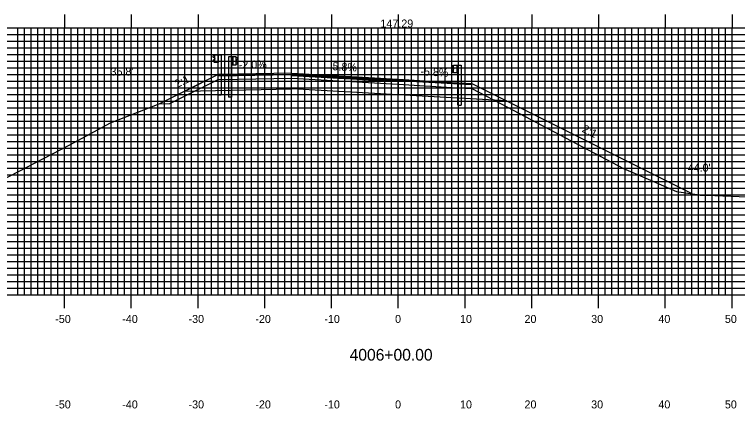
# Model space of a CAD drawing. Extents: x 851360 to 851703, y 364661 to 364881.
# Drawn here: x 851468.2 to 851576.6, y 364732.4 to 364791.4 of the extents above; entities that cross this region are included whole.
import ezdxf

# ---------------------------------------------------------------- set-up
doc = ezdxf.new("R2010")
doc.units = 0
for name, color, linetype in [('ANNOTATION', 7, 'Continuous'), ('D_Guardrail_Beam_Lt', 7, 'Continuous'), ('D_Guardrail_Beam_Rt', 7, 'Continuous'), ('D_Roadway_Centerline_Text', 7, 'Continuous'), ('D_Roadway_Edge_Shoulder', 7, 'Continuous'), ('D_Roadway_Edge_TW', 7, 'Continuous'), ('D_Roadway_Pavement', 7, 'Continuous'), ('D_Roadway_SlopeLines', 7, 'Continuous'), ('D_Roadway_SubGrade', 7, 'Continuous'), ('D_Text_Standard', 7, 'Continuous'), ('H_V ANNOTATION', 7, 'Continuous'), ('M_Guardrail', 7, 'Continuous'), ('M_Roadway_Centerline', 7, 'Continuous'), ('MAJOR', 7, 'Continuous'), ('MINOR', 7, 'Continuous'), ('S_Roadway_Centerline', 7, 'Continuous')]:
    doc.layers.add(name, color=color, linetype=linetype)

msp = doc.modelspace()

# ---------------------------------------------------------------- linework, layer by layer
at = {"layer": 'D_Guardrail_Beam_Lt'}
for p, q in [((851500.3, 364785.01), (851500.3, 364779.01)), ((851500.77, 364785.01), (851500.3, 364785.01)), ((851501.46, 364785.01), (851500.77, 364785.01)), ((851500.77, 364785.01), (851500.77, 364783.85)), ((851500.83, 364785.01), (851500.83, 364783.85)), ((851500.94, 364785.01), (851500.94, 364783.85)), ((851501.46, 364783.85), (851501.46, 364785.01)), ((851501.46, 364784.93), (851501.53, 364784.92)), ((851501.55, 364784.91), (851501.69, 364784.81)), ((851500.77, 364783.85), (851501.46, 364783.85)), ((851500.79, 364779.01), (851500.79, 364783.85)), ((851501.46, 364784.47), (851501.46, 364784.4)), ((851501.53, 364783.95), (851501.46, 364783.93)), ((851501.69, 364784.67), (851501.5, 364784.53)), ((851501.5, 364784.33), (851501.69, 364784.19)), ((851501.69, 364784.05), (851501.55, 364783.95)), ((851500.79, 364779.01), (851500.3, 364779.01))]:
    msp.add_line(p, q, dxfattribs=at)
for centre, major_axis, start_param, end_param in [((851501.52, 364784.88), (0.0417, 0), 0.959931, 1.376053), ((851501.54, 364784.47), (-0.0789, 0), 5.323254, 6.283185), ((851501.54, 364784.4), (-0.0789, 0), 6.283185, 7.243116), ((851501.52, 364783.99), (0.0417, 0), 4.907132, 5.323254), ((851501.64, 364784.74), (0.0877, 0), 5.323254, 7.243116), ((851501.64, 364784.12), (0.0877, 0), 5.323254, 7.243116)]:
    msp.add_ellipse(centre, major_axis=major_axis, ratio=0.995501, start_param=start_param, end_param=end_param, dxfattribs=at)
at = {"layer": 'D_Guardrail_Beam_Rt'}
for p, q in [((851534, 364783.78), (851534.69, 364783.78)), ((851534, 364782.62), (851534, 364783.78)), ((851534.52, 364783.78), (851534.52, 364782.62)), ((851534.62, 364783.78), (851534.62, 364782.62)), ((851534.69, 364783.78), (851535.16, 364783.78)), ((851534.69, 364783.78), (851534.69, 364782.62)), ((851535.16, 364783.78), (851535.16, 364777.78)), ((851533.91, 364783.68), (851533.77, 364783.58)), ((851533.77, 364783.43), (851533.96, 364783.3)), ((851533.96, 364783.1), (851533.77, 364782.96)), ((851533.77, 364782.82), (851533.91, 364782.72)), ((851534, 364783.7), (851533.93, 364783.68)), ((851533.93, 364782.71), (851534, 364782.7)), ((851534, 364783.23), (851534, 364783.16)), ((851534.69, 364782.62), (851534, 364782.62)), ((851534.67, 364777.78), (851534.67, 364782.62)), ((851534.67, 364777.78), (851535.16, 364777.78))]:
    msp.add_line(p, q, dxfattribs=at)
for centre, major_axis, start_param, end_param in [((851533.82, 364783.51), (-0.0877, 0), 5.323254, 7.243116), ((851533.82, 364782.89), (-0.0877, 0), 5.323254, 7.243116), ((851533.93, 364783.64), (-0.0417, 0), 4.907132, 5.323254), ((851533.93, 364782.75), (-0.0417, 0), 0.959931, 1.376053), ((851533.92, 364783.23), (0.0789, 0), 0, 0.959931), ((851533.92, 364783.16), (0.0789, 0), 5.323254, 6.283185)]:
    msp.add_ellipse(centre, major_axis=major_axis, ratio=0.995501, start_param=start_param, end_param=end_param, dxfattribs=at)
at = {"layer": 'D_Roadway_Edge_Shoulder'}
for points in [[(851509.73, 364782.59), (851501.73, 364782.43), (851501.73, 364782.43), (851498.73, 364782.37), (851498.73, 364782.2), (851509.73, 364782.39)], [(851525.73, 364781.66), (851533.73, 364781.2), (851533.73, 364781.2), (851536.73, 364781.02), (851536.73, 364780.86), (851525.73, 364781.5)]]:
    msp.add_lwpolyline(points, close=True, dxfattribs=at)
at = {"layer": 'D_Roadway_Edge_TW'}
msp.add_lwpolyline([(851509.73, 364782.59), (851525.73, 364781.66), (851525.73, 364781.5), (851509.73, 364782.39)], close=True, dxfattribs=at)
at = {"layer": 'D_Roadway_Pavement'}
msp.add_lwpolyline([(851509.73, 364782.39), (851525.73, 364781.5), (851525.73, 364781.33), (851509.73, 364782.23)], close=True, dxfattribs=at)
for points in [[(851509.73, 364782.39), (851509.73, 364782.23)], [(851525.73, 364781.5), (851525.73, 364781.33)], [(851525.73, 364781.5), (851525.73, 364781.33)], [(851525.73, 364781.5), (851525.73, 364781.33)]]:
    msp.add_lwpolyline(points, dxfattribs=at)
at = {"layer": 'D_Roadway_SlopeLines'}
for points in [[(851498.73, 364782.37), (851489.98, 364778)], [(851536.73, 364781.02), (851569.71, 364764.54)]]:
    msp.add_lwpolyline(points, dxfattribs=at)
at = {"layer": 'D_Roadway_SubGrade'}
for points in [[(851509.73, 364782.23), (851509.73, 364782.39), (851498.73, 364782.2), (851498.73, 364782.37), (851493.81, 364779.91), (851509.73, 364780.23)], [(851509.73, 364782.23), (851525.73, 364781.33), (851525.73, 364779.33), (851509.73, 364780.23)], [(851525.73, 364781.33), (851525.73, 364781.5), (851536.73, 364780.86), (851536.73, 364781.02), (851541.94, 364778.42), (851525.73, 364779.33)]]:
    msp.add_lwpolyline(points, close=True, dxfattribs=at)
at = {"layer": 'M_Guardrail'}
for p, q in [((851498.14, 364785.24), (851498, 364785.14)), ((851498, 364784.99), (851498.2, 364784.86)), ((851498.24, 364785.26), (851498.16, 364785.24)), ((851498.24, 364785.33), (851498.73, 364785.33)), ((851498.24, 364784.16), (851498.24, 364785.33)), ((851498.73, 364785.33), (851499.22, 364785.33)), ((851498.73, 364785.33), (851498.73, 364784.16)), ((851499.22, 364785.33), (851499.22, 364779.33)), ((851498.2, 364784.64), (851498, 364784.5)), ((851498, 364784.36), (851498.14, 364784.26)), ((851498.16, 364784.25), (851498.24, 364784.24)), ((851498.23, 364784.79), (851498.23, 364784.7)), ((851498.73, 364784.16), (851498.24, 364784.16)), ((851498.73, 364779.33), (851498.73, 364784.16)), ((851498.73, 364779.33), (851499.22, 364779.33))]:
    msp.add_line(p, q, dxfattribs=at)
for centre, major_axis, start_param, end_param in [((851498.05, 364785.06), (-0.0877, 0), 5.323254, 7.243116), ((851498.17, 364785.2), (-0.0417, 0), 4.886922, 5.323254), ((851498.15, 364784.79), (0.0789, 0), 0, 0.959931), ((851498.05, 364784.43), (-0.0877, 0), 5.323254, 7.243116), ((851498.17, 364784.29), (-0.0417, 0), 0.959931, 1.396263), ((851498.15, 364784.7), (0.0789, 0), 5.323254, 6.283185)]:
    msp.add_ellipse(centre, major_axis=major_axis, ratio=0.995501, start_param=start_param, end_param=end_param, dxfattribs=at)
at = {"layer": 'MAJOR'}
for p, q in [((851475.73, 364791.37), (851475.73, 364789.37)), ((851485.73, 364791.37), (851485.73, 364789.37)), ((851495.73, 364791.37), (851495.73, 364789.37)), ((851505.73, 364791.37), (851505.73, 364789.37)), ((851515.73, 364791.37), (851515.73, 364789.37)), ((851525.73, 364791.37), (851525.73, 364789.37)), ((851535.73, 364791.37), (851535.73, 364789.37)), ((851545.73, 364791.37), (851545.73, 364789.37)), ((851555.73, 364791.37), (851555.73, 364789.37)), ((851565.73, 364791.37), (851565.73, 364789.37)), ((851575.73, 364791.37), (851575.73, 364789.37)), ((851385.73, 364789.37), (851665.73, 364789.37)), ((851385.73, 364789.37), (851665.73, 364789.37)), ((851475.73, 364749.37), (851475.73, 364789.37)), ((851485.73, 364749.37), (851485.73, 364789.37)), ((851495.73, 364749.37), (851495.73, 364789.37)), ((851505.73, 364749.37), (851505.73, 364789.37)), ((851515.73, 364749.37), (851515.73, 364789.37)), ((851525.73, 364749.37), (851525.73, 364789.37)), ((851535.73, 364749.37), (851535.73, 364789.37)), ((851545.73, 364749.37), (851545.73, 364789.37)), ((851555.73, 364749.37), (851555.73, 364789.37)), ((851565.73, 364749.37), (851565.73, 364789.37)), ((851575.73, 364749.37), (851575.73, 364789.37)), ((851385.73, 364784.37), (851665.73, 364784.37)), ((851385.73, 364779.37), (851665.73, 364779.37)), ((851385.73, 364774.37), (851665.73, 364774.37)), ((851385.73, 364769.37), (851665.73, 364769.37)), ((851385.73, 364764.37), (851665.73, 364764.37)), ((851385.73, 364759.37), (851665.73, 364759.37)), ((851385.73, 364754.37), (851665.73, 364754.37)), ((851385.73, 364749.37), (851665.73, 364749.37)), ((851385.73, 364749.37), (851665.73, 364749.37)), ((851475.73, 364747.37), (851475.73, 364749.37)), ((851485.73, 364747.37), (851485.73, 364749.37)), ((851495.73, 364747.37), (851495.73, 364749.37)), ((851505.73, 364747.37), (851505.73, 364749.37)), ((851515.73, 364747.37), (851515.73, 364749.37)), ((851525.73, 364747.37), (851525.73, 364749.37)), ((851535.73, 364747.37), (851535.73, 364749.37)), ((851545.73, 364747.37), (851545.73, 364749.37)), ((851555.73, 364747.37), (851555.73, 364749.37)), ((851565.73, 364747.37), (851565.73, 364749.37)), ((851575.73, 364747.37), (851575.73, 364749.37))]:
    msp.add_line(p, q, dxfattribs=at)
at = {"layer": 'MINOR'}
for p, q in [((851468.73, 364749.37), (851468.73, 364789.37)), ((851469.73, 364749.37), (851469.73, 364789.37)), ((851470.73, 364749.37), (851470.73, 364789.37)), ((851471.73, 364749.37), (851471.73, 364789.37)), ((851472.73, 364749.37), (851472.73, 364789.37)), ((851473.73, 364749.37), (851473.73, 364789.37)), ((851474.73, 364749.37), (851474.73, 364789.37)), ((851476.73, 364749.37), (851476.73, 364789.37)), ((851477.73, 364749.37), (851477.73, 364789.37)), ((851478.73, 364749.37), (851478.73, 364789.37)), ((851479.73, 364749.37), (851479.73, 364789.37)), ((851480.73, 364749.37), (851480.73, 364789.37)), ((851481.73, 364749.37), (851481.73, 364789.37)), ((851482.73, 364749.37), (851482.73, 364789.37)), ((851483.73, 364749.37), (851483.73, 364789.37)), ((851484.73, 364749.37), (851484.73, 364789.37)), ((851486.73, 364749.37), (851486.73, 364789.37)), ((851487.73, 364749.37), (851487.73, 364789.37)), ((851488.73, 364749.37), (851488.73, 364789.37)), ((851489.73, 364749.37), (851489.73, 364789.37)), ((851490.73, 364749.37), (851490.73, 364789.37)), ((851491.73, 364749.37), (851491.73, 364789.37)), ((851492.73, 364749.37), (851492.73, 364789.37)), ((851493.73, 364749.37), (851493.73, 364789.37)), ((851494.73, 364749.37), (851494.73, 364789.37)), ((851496.73, 364749.37), (851496.73, 364789.37)), ((851497.73, 364749.37), (851497.73, 364789.37)), ((851498.73, 364749.37), (851498.73, 364789.37)), ((851499.73, 364749.37), (851499.73, 364789.37)), ((851500.73, 364749.37), (851500.73, 364789.37)), ((851501.73, 364749.37), (851501.73, 364789.37)), ((851502.73, 364749.37), (851502.73, 364789.37)), ((851503.73, 364749.37), (851503.73, 364789.37)), ((851504.73, 364749.37), (851504.73, 364789.37)), ((851506.73, 364749.37), (851506.73, 364789.37)), ((851507.73, 364749.37), (851507.73, 364789.37)), ((851508.73, 364749.37), (851508.73, 364789.37)), ((851509.73, 364749.37), (851509.73, 364789.37)), ((851510.73, 364749.37), (851510.73, 364789.37)), ((851511.73, 364749.37), (851511.73, 364789.37)), ((851512.73, 364749.37), (851512.73, 364789.37)), ((851513.73, 364749.37), (851513.73, 364789.37)), ((851514.73, 364749.37), (851514.73, 364789.37)), ((851516.73, 364749.37), (851516.73, 364789.37)), ((851517.73, 364749.37), (851517.73, 364789.37)), ((851518.73, 364749.37), (851518.73, 364789.37)), ((851519.73, 364749.37), (851519.73, 364789.37)), ((851520.73, 364749.37), (851520.73, 364789.37)), ((851521.73, 364749.37), (851521.73, 364789.37)), ((851522.73, 364749.37), (851522.73, 364789.37)), ((851523.73, 364749.37), (851523.73, 364789.37)), ((851524.73, 364749.37), (851524.73, 364789.37)), ((851526.73, 364749.37), (851526.73, 364789.37)), ((851527.73, 364749.37), (851527.73, 364789.37)), ((851528.73, 364749.37), (851528.73, 364789.37)), ((851529.73, 364749.37), (851529.73, 364789.37)), ((851530.73, 364749.37), (851530.73, 364789.37)), ((851531.73, 364749.37), (851531.73, 364789.37)), ((851532.73, 364749.37), (851532.73, 364789.37)), ((851533.73, 364749.37), (851533.73, 364789.37)), ((851534.73, 364749.37), (851534.73, 364789.37)), ((851536.73, 364749.37), (851536.73, 364789.37)), ((851537.73, 364749.37), (851537.73, 364789.37)), ((851538.73, 364749.37), (851538.73, 364789.37)), ((851539.73, 364749.37), (851539.73, 364789.37)), ((851540.73, 364749.37), (851540.73, 364789.37)), ((851541.73, 364749.37), (851541.73, 364789.37)), ((851542.73, 364749.37), (851542.73, 364789.37)), ((851543.73, 364749.37), (851543.73, 364789.37)), ((851544.73, 364749.37), (851544.73, 364789.37)), ((851546.73, 364749.37), (851546.73, 364789.37)), ((851547.73, 364749.37), (851547.73, 364789.37)), ((851548.73, 364749.37), (851548.73, 364789.37)), ((851549.73, 364749.37), (851549.73, 364789.37)), ((851550.73, 364749.37), (851550.73, 364789.37)), ((851551.73, 364749.37), (851551.73, 364789.37)), ((851552.73, 364749.37), (851552.73, 364789.37)), ((851553.73, 364749.37), (851553.73, 364789.37)), ((851554.73, 364749.37), (851554.73, 364789.37)), ((851556.73, 364749.37), (851556.73, 364789.37)), ((851557.73, 364749.37), (851557.73, 364789.37)), ((851558.73, 364749.37), (851558.73, 364789.37)), ((851559.73, 364749.37), (851559.73, 364789.37)), ((851560.73, 364749.37), (851560.73, 364789.37)), ((851561.73, 364749.37), (851561.73, 364789.37)), ((851562.73, 364749.37), (851562.73, 364789.37)), ((851563.73, 364749.37), (851563.73, 364789.37)), ((851564.73, 364749.37), (851564.73, 364789.37)), ((851566.73, 364749.37), (851566.73, 364789.37)), ((851567.73, 364749.37), (851567.73, 364789.37)), ((851568.73, 364749.37), (851568.73, 364789.37)), ((851569.73, 364749.37), (851569.73, 364789.37)), ((851570.73, 364749.37), (851570.73, 364789.37)), ((851571.73, 364749.37), (851571.73, 364789.37)), ((851572.73, 364749.37), (851572.73, 364789.37)), ((851573.73, 364749.37), (851573.73, 364789.37)), ((851574.73, 364749.37), (851574.73, 364789.37)), ((851385.73, 364788.37), (851665.73, 364788.37)), ((851385.73, 364787.37), (851665.73, 364787.37)), ((851385.73, 364786.37), (851665.73, 364786.37)), ((851385.73, 364785.37), (851665.73, 364785.37)), ((851385.73, 364783.37), (851665.73, 364783.37)), ((851385.73, 364782.37), (851665.73, 364782.37)), ((851385.73, 364781.37), (851665.73, 364781.37)), ((851385.73, 364780.37), (851665.73, 364780.37)), ((851385.73, 364778.37), (851665.73, 364778.37)), ((851385.73, 364777.37), (851665.73, 364777.37)), ((851385.73, 364776.37), (851665.73, 364776.37)), ((851385.73, 364775.37), (851665.73, 364775.37)), ((851385.73, 364773.37), (851665.73, 364773.37)), ((851385.73, 364772.37), (851665.73, 364772.37)), ((851385.73, 364771.37), (851665.73, 364771.37)), ((851385.73, 364770.37), (851665.73, 364770.37)), ((851385.73, 364768.37), (851665.73, 364768.37)), ((851385.73, 364767.37), (851665.73, 364767.37)), ((851385.73, 364766.37), (851665.73, 364766.37)), ((851385.73, 364765.37), (851665.73, 364765.37)), ((851385.73, 364763.37), (851665.73, 364763.37)), ((851385.73, 364762.37), (851665.73, 364762.37)), ((851385.73, 364761.37), (851665.73, 364761.37)), ((851385.73, 364760.37), (851665.73, 364760.37)), ((851385.73, 364758.37), (851665.73, 364758.37)), ((851385.73, 364757.37), (851665.73, 364757.37)), ((851385.73, 364756.37), (851665.73, 364756.37)), ((851385.73, 364755.37), (851665.73, 364755.37)), ((851385.73, 364753.37), (851665.73, 364753.37)), ((851385.73, 364752.37), (851665.73, 364752.37)), ((851385.73, 364751.37), (851665.73, 364751.37)), ((851385.73, 364750.37), (851665.73, 364750.37))]:
    msp.add_line(p, q, dxfattribs=at)
at = {"layer": 'S_Roadway_Centerline'}
for points in [[(851489.92, 364777.99), (851491.52, 364778.03), (851493.52, 364779.03), (851498.73, 364781.63), (851501.73, 364781.69), (851509.73, 364781.85), (851525.73, 364780.92), (851533.73, 364780.46), (851536.73, 364780.28), (851542.07, 364777.47), (851559.47, 364768.31)], [(851385.73, 364756.66), (851398.32, 364757.2), (851401.86, 364757.35), (851401.91, 364757.35), (851401.96, 364757.35), (851417.86, 364757.47), (851431.79, 364758.03), (851434.43, 364758.14), (851446.71, 364758.98), (851450.13, 364759.42), (851454.49, 364761.39), (851466.25, 364766.51), (851476.5, 364771.87), (851482.6, 364775.13), (851489.92, 364777.99)], [(851559.47, 364768.31), (851561.23, 364767.57), (851567.4, 364764.87), (851570.49, 364764.42), (851570.98, 364764.29), (851571.91, 364764.3), (851581.71, 364763.92), (851595.03, 364765.01), (851598.49, 364765.23), (851612.59, 364766.27), (851615.1, 364766.47), (851625.58, 364766.82), (851631.89, 364766.92), (851631.89, 364766.98), (851645.16, 364768.24), (851648.11, 364768.51), (851648.41, 364768.53), (851654.09, 364768.73), (851664.38, 364769.1), (851664.99, 364769.18), (851665.73, 364769.27)]]:
    msp.add_lwpolyline(points, dxfattribs=at)

# ---------------------------------------------------------------- texts
at = {"layer": 'ANNOTATION'}
for s, rotation, p in [('-2.0%', 1.1458, (851501.84, 364783.23)), ('5.8%', 356.6806, (851515.84, 364783.04)), ('-5.8%', 356.6806, (851529.02, 364782.28)), ('2:1', 26.5651, (851492.6, 364780.34)), ('2:1', 333.4349, (851553.15, 364773.85))]:
    msp.add_text(s, height=1.2, rotation=rotation, dxfattribs=at).set_placement(p)
at = {"layer": 'D_Roadway_Centerline_Text'}
msp.add_text('147.29', height=1.2, dxfattribs=at).set_placement((851523.06, 364789.42))
at = {"layer": 'D_Text_Standard'}
for s, p in [("35.8'", (851482.62, 364782.23)), ("44.0'", (851569.08, 364767.82))]:
    msp.add_text(s, height=1.2, dxfattribs=at).set_placement(p)
at = {"layer": 'H_V ANNOTATION'}
for s, height, p in [('-50', 1.2, (851474.34, 364745.17)), ('-40', 1.2, (851484.38, 364745.17)), ('-30', 1.2, (851494.31, 364745.17)), ('-20', 1.2, (851504.32, 364745.17)), ('-10', 1.2, (851514.66, 364745.17)), ('0', 1.2, (851525.25, 364745.17)), ('10', 1.2, (851534.98, 364745.17)), ('20', 1.2, (851544.64, 364745.17)), ('30', 1.2, (851554.63, 364745.17)), ('40', 1.2, (851564.7, 364745.17)), ('50', 1.2, (851574.66, 364745.17)), ('4006+00.00', 1.75, (851518.44, 364739.53)), ('-50', 1.2, (851474.34, 364732.37)), ('-40', 1.2, (851484.38, 364732.37)), ('-30', 1.2, (851494.31, 364732.37)), ('-20', 1.2, (851504.32, 364732.37)), ('-10', 1.2, (851514.66, 364732.37)), ('0', 1.2, (851525.25, 364732.37)), ('10', 1.2, (851534.98, 364732.37)), ('20', 1.2, (851544.64, 364732.37)), ('30', 1.2, (851554.63, 364732.37)), ('40', 1.2, (851564.7, 364732.37)), ('50', 1.2, (851574.66, 364732.37))]:
    msp.add_text(s, height=height, dxfattribs=at).set_placement(p)
at = {"layer": 'M_Roadway_Centerline'}
for s, p in [('C', (851514.12, 364780.41)), ('L', (851514.13, 364780.4))]:
    msp.add_text(s, height=0.0146, dxfattribs=at).set_placement(p)

doc.saveas('drawing.dxf')
